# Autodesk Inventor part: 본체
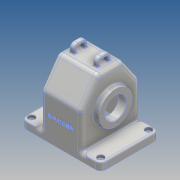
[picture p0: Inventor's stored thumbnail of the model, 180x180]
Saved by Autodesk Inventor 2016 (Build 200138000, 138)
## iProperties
Created: 2016-12
Part Number: 본체
Material: 알루미늄 6061
Document SubType Name: Modeling
Designer: Administrator
Density: 2.7 g/cm^3
Appearance: 알루미늄 - 평지
Mass: 1051.15 g
Surface Area: 1136.66 cm^2
Volume: 389.314 cm^3
Author: Administrator
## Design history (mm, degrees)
sketch "스케치1"
  geometry: L1 (-75, 55)-(75, 55); L2 (75, 55)-(75, -55); L3 (75, -55)-(-75, -55); L4 (-75, -55)-(-75, 55); L5 (-75, 55)-(75, -55); L6 (75, 55)-(-75, -55); 1 further point
  constraints: 12 end point, 2 midpoint, 2 parallel, 1 horizontal, 1 perpendicular
  dimensions: "d0" = 150 distance of L2.end L3.end; "d1" = 110 distance of L1.end L2.end
extrude "돌출1" new body sketch "스케치1" distance "d2" = 15; taper "d3" = 0 deg
fillet "모깎기1" dims "d4" = 10
sketch "스케치2"
  geometry: A1 r 10 centre (65, -45) between (65, -55) and (75, -45) reference; A2 r 10 centre (65, 45) between (75, 45) and (65, 55) reference; A3 r 10 centre (-65, 45) between (-65, 55) and (-75, 45) reference; A4 r 10 centre (-65, -45) between (-75, -45) and (-65, -55) reference; 5 further points
  constraints: 4 coincident
hole "구멍1" sketch "스케치2" at (-65, 45), (-65, -45), (65, -45), (65, 45) diameter "d5" = 5; stored, may be unused: countersink angle "d9" = 90 deg, drill point angle "d11" = 118 deg; dims "d6" = 6, "d7" = 12, "d8" = 5, "d10" = 8
sketch "스케치3"
  geometry: L1 (-65, 15)-(65, 15) reference; L2 (38.5, 15)-(38.5, 125); L3 (38.5, 125)-(-38.5, 125); L4 (-38.5, 125)-(-38.5, 15); L5 (65, 0)-(-65, 0) reference; 3 further points
  constraints: 6 end point, 2 midpoint, 2 point on line, 2 vertical, 1 horizontal, 1 vertical alignment
  dimensions: "d12" = 77 distance between parallel lines of L4 L2; "d13" = 125 distance between parallel lines of L5 L3
extrude "돌출2" join sketch "스케치3" stored distance "d14" = 110; taper "d15" = 0 deg
sketch "스케치4"
  geometry: L1 (-110, 110)-(0, 110) reference; L2 (-110, 0)-(-110, 110) reference; L3 (0, 0)-(-110, 0) reference; L4 (-65, 0)-(-110, 31.509); L5 (-110, 78.491)-(-65, 110); L6 (15, 110)-(15, 100) reference; L7 (15, 100)-(15, 10) reference; 1 further point
  constraints: 4 end point, 4 point on line, 1 equal length
  dimensions: "d16" = 80 distance from line of L6 L5.end; "d17" = 80 distance from line of L7 L4.start; "d18" = 35 deg angle of L4 L3
extrude "돌출3" cut sketch "스케치4" stored distance "d19" = 110; taper "d20" = 0 deg
node "작업 평면1"
sketch "스케치5"
  geometry: L1 (-15, 10)-(0, 10) reference; L2 (-15, 100)-(-15, 10) reference; L3 (0, 100)-(-15, 100) reference; L4 (0, 10)-(0, 100) reference; L5 (-15, 100)-(-15, 10) reference; C1 r 31 at (50, 55); 2 further points
  constraints: 1 centre point, 1 horizontal alignment, 1 midpoint
  dimensions: "d22" = 62 diameter of C1; "d23" = 65 distance from line of L2 C1.centre
extrude "돌출4" join sketch "스케치5" stored distance "d24" = 0; taper "d25" = 0 deg
node "작업 평면2"
sketch "스케치6"
  geometry: L1 (-15, 10)-(-15, 100) reference; C1 r 37.5 at (50, 55); 2 further points
  constraints: 1 centre point, 1 horizontal alignment, 1 midpoint
  dimensions: "d27" = 75 diameter of C1; "d28" = 65 distance from line of L1 C1.centre
extrude "돌출5" join sketch "스케치6" stored distance "d29" = 110; taper "d30" = 0 deg
sketch "스케치10"
  geometry: L1 (50, 0)-(50, 78.424); L2 (50, 78.424)-(20.888, 120); L3 (20.888, 120)-(-20.888, 120); L4 (-20.888, 120)-(-50, 78.424); L5 (-50, 78.424)-(-50, 0); L6 (45, 0)-(-45, 0) reference; L7 (-55, 15)-(-55, 80) reference; L8 (-23.491, 125)-(-55, 80) reference; L9 (-23.491, 125)-(23.491, 125) reference; L10 (55, 80)-(23.491, 125) reference; L11 (55, 80)-(55, 15) reference; L12 (50, 0)-(-50, 0); 1 further point
  constraints: 12 end point, 2 horizontal, 2 parallel, 2 point on line, 2 vertical, 1 horizontal alignment
  dimensions: "d43" = 5 distance between parallel lines of L5 L7; "d44" = 5 distance between parallel lines of L1 L11; "d45" = 5 distance between parallel lines of L3 L9; "d48" = 5 distance between parallel lines of L8 L4
extrude "돌출6" cut sketch "스케치10" stored distance "d49" = 67; taper "d50" = 0 deg
sketch "스케치11"
  geometry: L1 (43.5, 65)-(-86.441, 65); L2 (33.5, 120)-(33.5, 78.424) reference; L3 (33.5, 106)-(19.5, 92); L4 (19.5, 92)-(19.5, 65); L5 (33.5, 106)-(33.5, 65); L6 (43.5, 102.5)-(43.5, 27.5) reference; 1 further point
  constraints: 8 end point, 3 point on line, 1 horizontal, 1 perpendicular, 1 vertical
  dimensions: "d53" = 54 diameter of L3.end L1; "d54" = 45 deg angle of L4 L3; "d98" = 24 distance between parallel lines of L6 L4; "d100" = 65 vertical distance of point (0, 0) L4.end
revolve "회전1" sketch "스케치11" stored, may be unused: angle "d56" = 90 deg
hole "구멍3" diameter "d59" = 40; stored, may be unused: countersink angle "d63" = 90 deg, drill point angle "d65" = 118 deg; dims "d57" = 10, "d58" = 10, "d60" = 6, "d61" = 12, "d62" = 5, "d64" = 8
sketch "스케치12"
  geometry: C1 r 20 at (0, 0) reference; 5 further points
  constraints: 2 horizontal alignment, 2 vertical alignment
  dimensions: "d66" = 52 distance of point (26, 0) point (-26, 0); "d67" = 26 distance of point (-26, 0) C1.centre; "d68" = 52 distance of point (0, -26) point (0, 26); "d69" = 26 distance of point (0, -26) C1.centre
hole "구멍4" sketch "스케치12" at (-26, 0), (0, -26), (0, 26), (26, 0) diameter "d70" = 2.459; stored, may be unused: countersink angle "d74" = 90 deg, drill point angle "d76" = 118 deg; dims "d71" = 6, "d72" = 12, "d73" = 5, "d75" = 8
sketch "스케치13"
  geometry: C1 r 20 at (0, 0) reference; 5 further points
  constraints: 2 horizontal alignment, 2 vertical alignment
  dimensions: "d77" = 58 distance of point (-29, 0) point (29, 0); "d78" = 58 distance of point (0, -29) point (0, 29); "d79" = 29 distance of C1.centre point (29, 0); "d80" = 29 distance of point (0, -29) C1.centre
hole "구멍5" sketch "스케치13" at (29, 0), (0, 29), (-29, 0), (0, -29) diameter "d81" = 2.459; stored, may be unused: countersink angle "d85" = 90 deg, drill point angle "d87" = 118 deg; dims "d82" = 6, "d83" = 12, "d84" = 5, "d86" = 8
node "작업 평면3"
sketch "스케치14"
  geometry: L1 (55, 80)-(23.491, 125) reference; L2 (-23.491, 125)-(23.491, 125) reference; L3 (-23.491, 125)-(-55, 80) reference; L4 (-55, 15)-(-55, 80) reference; L5 (55, 15)-(-55, 15) reference; L6 (55, 80)-(55, 15) reference; L7 (-23.491, 125)-(23.491, 125) reference; L8 (-12.5, 125)-(-12.5, 140); L9 (-12.5, 140)-(12.5, 140); L10 (12.5, 140)-(12.5, 125); L11 (-7.5, 125)-(-7.5, 135); L12 (-7.5, 135)-(7.5, 135); L13 (7.5, 135)-(7.5, 125); L14 (45, 0)-(-45, 0) reference; C1 r 31 at (0, 65) reference; 3 further points
  constraints: 12 end point, 4 point on line, 3 perpendicular, 3 vertical, 2 midpoint, 2 vertical alignment
  dimensions: "d89" = 25 distance between parallel lines of L8 L10; "d90" = 15 distance between parallel lines of L11 L13; "d91" = 140 distance between parallel lines of L14 L9; "d92" = 5 distance between parallel lines of L12 L9
extrude "돌출7" join sketch "스케치14" distance "d93" = 8; taper "d94" = 0 deg
fillet "모깎기3" dims "d96" = 1
fillet "모깎기4" dims "d97" = 8
fillet "모깎기5" dims "d101" = 1, "d113" = 3
fillet "모깎기6" dims "d102" = 3
fillet "모깎기7" dims "d103" = 3
node "작업 평면5"
sketch "스케치15"
  geometry: L1 (-38.5, 77.478)-(-38.5, 18) reference; 2 further points
  constraints: 1 other
  dimensions: "d105" = 45 distance of point (0, 0) point (0, 45); "d106" = 38.5 distance from line of L1 point (0, 45)
feature "엠보싱1" sketch "스케치15" dims "d0" = 150, "d1" = 110, "d107" = 0.5, "d108" = 0
chamfer "모따기1" distance "d109" = 1; stored, may be unused: second distance "d110" = 2, angle "d111" = 45 deg
fillet "모깎기9" dims "d114" = 3
fillet "모깎기10" dims "d115" = 10
fillet "모깎기11" dims "d116" = 8
node "솔리드1"
mirror "대칭1"
node "투영된 루프1"
node "투영된 루프2"
node "작업 평면4"
other parameters: "d21" = -87, "d26" = 5, "d88" = 26
